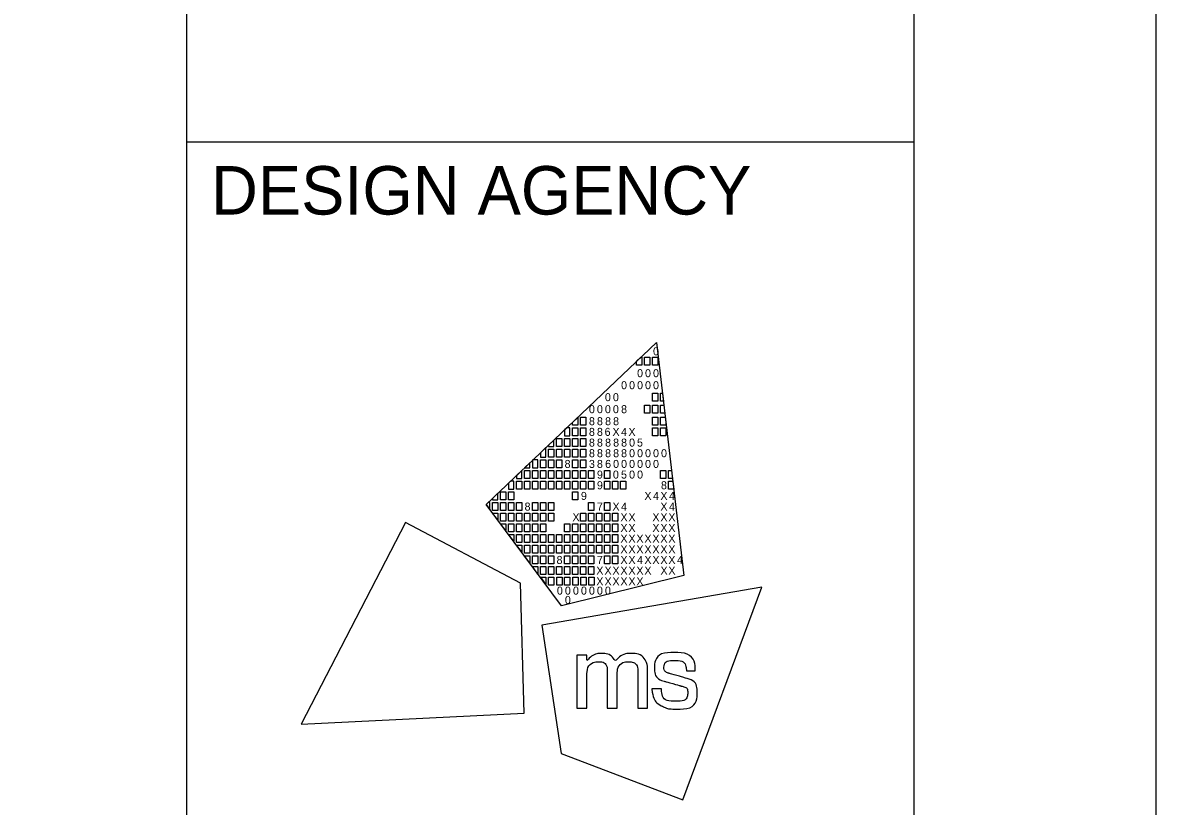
# Model space of a CAD drawing. Extents: x -3.4 to 34, y 0 to 22.
# Drawn here: x 31.661 to 34, y 3.129 to 4.746 of the extents above; entities that cross this region are included whole.
import ezdxf

# ---------------------------------------------------------------- set-up
doc = ezdxf.new("R2010")
doc.units = 0
for name, color, linetype in [('Default', 7, 'Continuous'), ('SH_Border', 7, 'Continuous'), ('SH_Cut_Line', 7, 'Continuous'), ('SH_Data', 7, 'Continuous')]:
    doc.layers.add(name, color=color, linetype=linetype)

msp = doc.modelspace()

# ---------------------------------------------------------------- linework, layer by layer
at = {"layer": 'Default'}
for p, q in [((32.6175, 3.7519), (32.9688, 4.0861)), ((32.9688, 4.0861), (32.9688, 4.0861)), ((32.9688, 4.0861), (33.0253, 3.6052)), ((32.773, 3.543), (32.6175, 3.7519)), ((33.0253, 3.6052), (32.773, 3.543))]:
    msp.add_line(p, q, dxfattribs=at)
for points in [[(32.9279, 4.0472), (32.9369, 4.0558), (32.9389, 4.0558), (32.9389, 4.0393), (32.9279, 4.0393)], [(32.9444, 4.0558), (32.9554, 4.0558), (32.9554, 4.0393), (32.9444, 4.0393)], [(32.9609, 4.0558), (32.9719, 4.0558), (32.9719, 4.0393), (32.9609, 4.0393)], [(32.9606, 3.9815), (32.9716, 3.9815), (32.9716, 3.965), (32.9606, 3.965)], [(32.9771, 3.9815), (32.9811, 3.9815), (32.983, 3.965), (32.9771, 3.965)], [(32.9441, 3.9567), (32.9551, 3.9567), (32.9551, 3.9402), (32.9441, 3.9402)], [(32.9606, 3.9567), (32.9716, 3.9567), (32.9716, 3.9402), (32.9606, 3.9402)], [(32.9771, 3.9567), (32.984, 3.9567), (32.9859, 3.9402), (32.9771, 3.9402)], [(32.7953, 3.9211), (32.8064, 3.9316), (32.8064, 3.9154), (32.7953, 3.9154)], [(32.8123, 3.9319), (32.8233, 3.9319), (32.8233, 3.9154), (32.8123, 3.9154)], [(32.9606, 3.9319), (32.9716, 3.9319), (32.9716, 3.9154), (32.9606, 3.9154)], [(32.9771, 3.9319), (32.9869, 3.9319), (32.9881, 3.9218), (32.9881, 3.9154), (32.9771, 3.9154)], [(32.7958, 3.9099), (32.8068, 3.9099), (32.8068, 3.8934), (32.7958, 3.8934)], [(32.8123, 3.9099), (32.8233, 3.9099), (32.8233, 3.8934), (32.8123, 3.8934)], [(32.9606, 3.9099), (32.9716, 3.9099), (32.9716, 3.8934), (32.9606, 3.8934)], [(32.9771, 3.9099), (32.9881, 3.9099), (32.9881, 3.8934), (32.9771, 3.8934)], [(32.7627, 3.8879), (32.7737, 3.8879), (32.7737, 3.8714), (32.7627, 3.8714)], [(32.7793, 3.8879), (32.7903, 3.8879), (32.7903, 3.8714), (32.7793, 3.8714)], [(32.7958, 3.8879), (32.8068, 3.8879), (32.8068, 3.8714), (32.7958, 3.8714)], [(32.8123, 3.8879), (32.8233, 3.8879), (32.8233, 3.8714), (32.8123, 3.8714)], [(32.7462, 3.8659), (32.7572, 3.8659), (32.7572, 3.8494), (32.7462, 3.8494)], [(32.7627, 3.8659), (32.7737, 3.8659), (32.7737, 3.8494), (32.7627, 3.8494)], [(32.7793, 3.8659), (32.7903, 3.8659), (32.7903, 3.8494), (32.7793, 3.8494)], [(32.7958, 3.8659), (32.8068, 3.8659), (32.8068, 3.8494), (32.7958, 3.8494)], [(32.8123, 3.8659), (32.8233, 3.8659), (32.8233, 3.8494), (32.8123, 3.8494)], [(32.7297, 3.8439), (32.7407, 3.8439), (32.7407, 3.8273), (32.7297, 3.8273)], [(32.7462, 3.8439), (32.7572, 3.8439), (32.7572, 3.8273), (32.7462, 3.8273)], [(32.7627, 3.8439), (32.7737, 3.8439), (32.7737, 3.8273), (32.7627, 3.8273)], [(32.7958, 3.8439), (32.8068, 3.8439), (32.8068, 3.8273), (32.7958, 3.8273)], [(32.8123, 3.8439), (32.8233, 3.8439), (32.8233, 3.8273), (32.8123, 3.8273)], [(32.6967, 3.8218), (32.7077, 3.8218), (32.7077, 3.8053), (32.6967, 3.8053)], [(32.7132, 3.8218), (32.7242, 3.8218), (32.7242, 3.8053), (32.7132, 3.8053)], [(32.7297, 3.8218), (32.7407, 3.8218), (32.7407, 3.8053), (32.7297, 3.8053)], [(32.7462, 3.8218), (32.7572, 3.8218), (32.7572, 3.8053), (32.7462, 3.8053)], [(32.7627, 3.8218), (32.7737, 3.8218), (32.7737, 3.8053), (32.7627, 3.8053)], [(32.7793, 3.8218), (32.7903, 3.8218), (32.7903, 3.8053), (32.7793, 3.8053)], [(32.7958, 3.8218), (32.8068, 3.8218), (32.8068, 3.8053), (32.7958, 3.8053)], [(32.8123, 3.8218), (32.8233, 3.8218), (32.8233, 3.8053), (32.8123, 3.8053)], [(32.8288, 3.8218), (32.8398, 3.8218), (32.8398, 3.8053), (32.8288, 3.8053)], [(32.8618, 3.8218), (32.8728, 3.8218), (32.8728, 3.8053), (32.8618, 3.8053)], [(32.9771, 3.8218), (32.9881, 3.8218), (32.9881, 3.8053), (32.9771, 3.8053)], [(32.9935, 3.8218), (32.9998, 3.8218), (33.0018, 3.8053), (32.9935, 3.8053)], [(32.6802, 3.7998), (32.6912, 3.7998), (32.6912, 3.7833), (32.6802, 3.7833)], [(32.6967, 3.7998), (32.7077, 3.7998), (32.7077, 3.7833), (32.6967, 3.7833)], [(32.7132, 3.7998), (32.7242, 3.7998), (32.7242, 3.7833), (32.7132, 3.7833)], [(32.7297, 3.7998), (32.7407, 3.7998), (32.7407, 3.7833), (32.7297, 3.7833)], [(32.7462, 3.7998), (32.7572, 3.7998), (32.7572, 3.7833), (32.7462, 3.7833)], [(32.7627, 3.7998), (32.7737, 3.7998), (32.7737, 3.7833), (32.7627, 3.7833)], [(32.7793, 3.7998), (32.7903, 3.7998), (32.7903, 3.7833), (32.7793, 3.7833)], [(32.7958, 3.7998), (32.8068, 3.7998), (32.8068, 3.7833), (32.7958, 3.7833)], [(32.8123, 3.7998), (32.8233, 3.7998), (32.8233, 3.7833), (32.8123, 3.7833)], [(32.8288, 3.7998), (32.8398, 3.7998), (32.8398, 3.7833), (32.8288, 3.7833)], [(32.8618, 3.7998), (32.8728, 3.7998), (32.8728, 3.7833), (32.8618, 3.7833)], [(32.8783, 3.7998), (32.8893, 3.7998), (32.8893, 3.7833), (32.8783, 3.7833)], [(32.8947, 3.7998), (32.9057, 3.7998), (32.9057, 3.7833), (32.8947, 3.7833)], [(32.9935, 3.7998), (33.0024, 3.7998), (33.0044, 3.7833), (32.9935, 3.7833)], [(32.6471, 3.7778), (32.6581, 3.7778), (32.6581, 3.7613), (32.6471, 3.7613)], [(32.6637, 3.7778), (32.6747, 3.7778), (32.6747, 3.7613), (32.6637, 3.7613)], [(32.7958, 3.7778), (32.8068, 3.7778), (32.8068, 3.7613), (32.7958, 3.7613)], [(32.6306, 3.7558), (32.6416, 3.7558), (32.6416, 3.7393), (32.6306, 3.7393)], [(32.6471, 3.7558), (32.6581, 3.7558), (32.6581, 3.7393), (32.6471, 3.7393)], [(32.6637, 3.7558), (32.6747, 3.7558), (32.6747, 3.7393), (32.6637, 3.7393)], [(32.6802, 3.7558), (32.6912, 3.7558), (32.6912, 3.7393), (32.6802, 3.7393)], [(32.7132, 3.7558), (32.7242, 3.7558), (32.7242, 3.7393), (32.7132, 3.7393)], [(32.7297, 3.7558), (32.7407, 3.7558), (32.7407, 3.7393), (32.7297, 3.7393)], [(32.7462, 3.7558), (32.7572, 3.7558), (32.7572, 3.7393), (32.7462, 3.7393)], [(32.8288, 3.7558), (32.8398, 3.7558), (32.8398, 3.7393), (32.8288, 3.7393)], [(32.8618, 3.7558), (32.8728, 3.7558), (32.8728, 3.7393), (32.8618, 3.7393)], [(32.6306, 3.7338), (32.6416, 3.7338), (32.6416, 3.72)], [(32.6471, 3.7338), (32.6581, 3.7338), (32.6581, 3.7173), (32.6471, 3.7173)], [(32.6637, 3.7338), (32.6747, 3.7338), (32.6747, 3.7173), (32.6637, 3.7173)], [(32.6802, 3.7338), (32.6912, 3.7338), (32.6912, 3.7173), (32.6802, 3.7173)], [(32.6967, 3.7338), (32.7077, 3.7338), (32.7077, 3.7173), (32.6967, 3.7173)], [(32.7132, 3.7338), (32.7242, 3.7338), (32.7242, 3.7173), (32.7132, 3.7173)], [(32.7297, 3.7338), (32.7407, 3.7338), (32.7407, 3.7173), (32.7297, 3.7173)], [(32.7462, 3.7338), (32.7572, 3.7338), (32.7572, 3.7173), (32.7462, 3.7173)], [(32.8123, 3.7338), (32.8233, 3.7338), (32.8233, 3.7173), (32.8123, 3.7173)], [(32.8288, 3.7338), (32.8398, 3.7338), (32.8398, 3.7173), (32.8288, 3.7173)], [(32.8453, 3.7338), (32.8563, 3.7338), (32.8563, 3.7173), (32.8453, 3.7173)], [(32.8618, 3.7338), (32.8728, 3.7338), (32.8728, 3.7173), (32.8618, 3.7173)], [(32.8783, 3.7338), (32.8893, 3.7338), (32.8893, 3.7173), (32.8783, 3.7173)], [(32.6471, 3.7117), (32.6581, 3.7117), (32.6581, 3.698)], [(32.6637, 3.7117), (32.6747, 3.7117), (32.6747, 3.6952), (32.6637, 3.6952)], [(32.6802, 3.7117), (32.6912, 3.7117), (32.6912, 3.6952), (32.6802, 3.6952)], [(32.6967, 3.7117), (32.7077, 3.7117), (32.7077, 3.6952), (32.6967, 3.6952)], [(32.7132, 3.7117), (32.7242, 3.7117), (32.7242, 3.6952), (32.7132, 3.6952)], [(32.7297, 3.7117), (32.7407, 3.7117), (32.7407, 3.6952), (32.7297, 3.6952)], [(32.7793, 3.7117), (32.7903, 3.7117), (32.7903, 3.6952), (32.7793, 3.6952)], [(32.7958, 3.7117), (32.8068, 3.7117), (32.8068, 3.6952), (32.7958, 3.6952)], [(32.8123, 3.7117), (32.8233, 3.7117), (32.8233, 3.6952), (32.8123, 3.6952)], [(32.8288, 3.7117), (32.8398, 3.7117), (32.8398, 3.6952), (32.8288, 3.6952)], [(32.8453, 3.7117), (32.8563, 3.7117), (32.8563, 3.6952), (32.8453, 3.6952)], [(32.8618, 3.7117), (32.8728, 3.7117), (32.8728, 3.6952), (32.8618, 3.6952)], [(32.8783, 3.7117), (32.8893, 3.7117), (32.8893, 3.6952), (32.8783, 3.6952)], [(32.6637, 3.6897), (32.6747, 3.6897), (32.6747, 3.676)], [(32.6747, 3.6897), (32.6747, 3.6897), (32.6747, 3.6897)], [(32.6802, 3.6897), (32.6912, 3.6897), (32.6912, 3.6732), (32.6802, 3.6732)], [(32.6967, 3.6897), (32.7077, 3.6897), (32.7077, 3.6732), (32.6967, 3.6732)], [(32.7132, 3.6897), (32.7242, 3.6897), (32.7242, 3.6732), (32.7132, 3.6732)], [(32.7297, 3.6897), (32.7407, 3.6897), (32.7407, 3.6732), (32.7297, 3.6732)], [(32.7462, 3.6897), (32.7572, 3.6897), (32.7572, 3.6732), (32.7462, 3.6732)], [(32.7627, 3.6897), (32.7737, 3.6897), (32.7737, 3.6732), (32.7627, 3.6732)], [(32.7793, 3.6897), (32.7903, 3.6897), (32.7903, 3.6732), (32.7793, 3.6732)], [(32.7958, 3.6897), (32.8068, 3.6897), (32.8068, 3.6732), (32.7958, 3.6732)], [(32.8123, 3.6897), (32.8233, 3.6897), (32.8233, 3.6732), (32.8123, 3.6732)], [(32.8288, 3.6897), (32.8398, 3.6897), (32.8398, 3.6732), (32.8288, 3.6732)], [(32.8453, 3.6897), (32.8563, 3.6897), (32.8563, 3.6732), (32.8453, 3.6732)], [(32.8618, 3.6897), (32.8728, 3.6897), (32.8728, 3.6732), (32.8618, 3.6732)], [(32.8783, 3.6897), (32.8893, 3.6897), (32.8893, 3.6732), (32.8783, 3.6732)], [(32.6802, 3.6677), (32.6912, 3.6677), (32.6912, 3.654)], [(32.6967, 3.6677), (32.7077, 3.6677), (32.7077, 3.6512), (32.6967, 3.6512)], [(32.7132, 3.6677), (32.7242, 3.6677), (32.7242, 3.6512), (32.7132, 3.6512)], [(32.7297, 3.6677), (32.7407, 3.6677), (32.7407, 3.6512), (32.7297, 3.6512)], [(32.7462, 3.6677), (32.7572, 3.6677), (32.7572, 3.6512), (32.7462, 3.6512)], [(32.7627, 3.6677), (32.7737, 3.6677), (32.7737, 3.6512), (32.7627, 3.6512)], [(32.7793, 3.6677), (32.7903, 3.6677), (32.7903, 3.6512), (32.7793, 3.6512)], [(32.7958, 3.6677), (32.8068, 3.6677), (32.8068, 3.6512), (32.7958, 3.6512)], [(32.8123, 3.6677), (32.8233, 3.6677), (32.8233, 3.6512), (32.8123, 3.6512)], [(32.8288, 3.6677), (32.8398, 3.6677), (32.8398, 3.6512), (32.8288, 3.6512)], [(32.8453, 3.6677), (32.8563, 3.6677), (32.8563, 3.6512), (32.8453, 3.6512)], [(32.8618, 3.6677), (32.8728, 3.6677), (32.8728, 3.6512), (32.8618, 3.6512)], [(32.8783, 3.6677), (32.8893, 3.6677), (32.8893, 3.6512), (32.8783, 3.6512)], [(32.7077, 3.6305), (32.6965, 3.6457), (32.7077, 3.6457)], [(32.7132, 3.6457), (32.7242, 3.6457), (32.7242, 3.6292), (32.7132, 3.6292)], [(32.7297, 3.6457), (32.7407, 3.6457), (32.7407, 3.6292), (32.7297, 3.6292)], [(32.7462, 3.6457), (32.7572, 3.6457), (32.7572, 3.6292), (32.7462, 3.6292)], [(32.7793, 3.6457), (32.7903, 3.6457), (32.7903, 3.6292), (32.7793, 3.6292)], [(32.7958, 3.6457), (32.8068, 3.6457), (32.8068, 3.6292), (32.7958, 3.6292)], [(32.8123, 3.6457), (32.8233, 3.6457), (32.8233, 3.6292), (32.8123, 3.6292)], [(32.8288, 3.6457), (32.8398, 3.6457), (32.8398, 3.6292), (32.8288, 3.6292)], [(32.8618, 3.6457), (32.8728, 3.6457), (32.8728, 3.6292), (32.8618, 3.6292)], [(32.8783, 3.6457), (32.8893, 3.6457), (32.8893, 3.6292), (32.8783, 3.6292)], [(32.724, 3.6082), (32.7132, 3.6237), (32.7242, 3.6237)], [(32.7297, 3.6237), (32.7407, 3.6237), (32.7407, 3.6072), (32.7297, 3.6072)], [(32.7302, 3.6017), (32.7407, 3.6017), (32.7408, 3.5875)], [(32.7462, 3.6237), (32.7572, 3.6237), (32.7572, 3.6072), (32.7462, 3.6072)], [(32.7463, 3.6017), (32.7573, 3.6017), (32.7573, 3.5852), (32.7463, 3.5852)], [(32.7627, 3.6237), (32.7737, 3.6237), (32.7737, 3.6072), (32.7627, 3.6072)], [(32.763, 3.6017), (32.774, 3.6017), (32.774, 3.5852), (32.763, 3.5852)], [(32.7793, 3.6237), (32.7903, 3.6237), (32.7903, 3.6072), (32.7793, 3.6072)], [(32.7794, 3.6017), (32.7904, 3.6017), (32.7904, 3.5852), (32.7794, 3.5852)], [(32.7958, 3.6237), (32.8068, 3.6237), (32.8068, 3.6072), (32.7958, 3.6072)], [(32.796, 3.6017), (32.807, 3.6017), (32.807, 3.5852), (32.796, 3.5852)], [(32.8123, 3.6237), (32.8233, 3.6237), (32.8233, 3.6072), (32.8123, 3.6072)], [(32.8129, 3.6017), (32.8239, 3.6017), (32.8239, 3.5851), (32.8129, 3.5851)], [(32.8288, 3.6237), (32.8398, 3.6237), (32.8398, 3.6072), (32.8288, 3.6072)], [(32.8296, 3.6017), (32.8406, 3.6017), (32.8406, 3.5851), (32.8296, 3.5851)]]:
    msp.add_lwpolyline(points, close=True, dxfattribs=at)
for points in [[(32.7903, 3.9099), (32.7836, 3.9099), (32.7793, 3.9058), (32.7793, 3.8934), (32.7903, 3.8934), (32.7903, 3.9099)], [(32.7572, 3.8849), (32.7462, 3.8744), (32.7462, 3.8714), (32.7572, 3.8714), (32.7572, 3.8849)], [(32.7407, 3.8691), (32.7297, 3.8587), (32.7297, 3.8494), (32.7407, 3.8494), (32.7407, 3.8691)], [(32.7077, 3.8377), (32.6968, 3.8273), (32.7077, 3.8273), (32.7077, 3.8377)], [(32.7242, 3.8439), (32.7141, 3.8439), (32.7132, 3.843), (32.7132, 3.8273), (32.7242, 3.8273), (32.7242, 3.8439)], [(32.6912, 3.822), (32.6802, 3.8115), (32.6802, 3.8053), (32.6912, 3.8053), (32.6912, 3.822)], [(32.6747, 3.7998), (32.6679, 3.7998), (32.6637, 3.7958), (32.6637, 3.7833), (32.6747, 3.7833), (32.6747, 3.7998)], [(32.6416, 3.7749), (32.6306, 3.7644), (32.6306, 3.7613), (32.6416, 3.7613), (32.6416, 3.7749)], [(32.6251, 3.7558), (32.6216, 3.7558), (32.6175, 3.7519), (32.6251, 3.7417), (32.6251, 3.7558)], [(32.4512, 3.7149), (32.2359, 3.2988), (32.6956, 3.3215), (32.6884, 3.5892), (32.4512, 3.7149)], [(33.0229, 3.1422), (33.1859, 3.5814), (32.7324, 3.5029), (32.7722, 3.2381), (33.0229, 3.1422)]]:
    msp.add_lwpolyline(points, dxfattribs=at)
for points in [[(32.8048, 3.3315), (32.8048, 3.3315), (32.8048, 3.4409), (32.8048, 3.4409), (32.8048, 3.4409), (32.8255, 3.4409), (32.8255, 3.4409), (32.8255, 3.4409), (32.8255, 3.4297), (32.8255, 3.4297), (32.8346, 3.4399), (32.8457, 3.4445), (32.8555, 3.4445), (32.8688, 3.4445), (32.8791, 3.4372), (32.8837, 3.4266), (32.8915, 3.4381), (32.905, 3.4446), (32.9166, 3.4446), (32.9325, 3.4446), (32.9451, 3.435), (32.9494, 3.4213), (32.9494, 3.4212), (32.9494, 3.4212), (32.9494, 3.4212), (32.9501, 3.419), (32.9506, 3.4172), (32.9506, 3.4071), (32.9506, 3.4071), (32.9506, 3.3314), (32.9506, 3.3314), (32.9506, 3.3314), (32.9303, 3.3314), (32.9303, 3.3314), (32.9303, 3.3314), (32.9303, 3.4048), (32.9303, 3.4048), (32.9303, 3.4201), (32.9219, 3.4274), (32.911, 3.4274), (32.8995, 3.4274), (32.8879, 3.4171), (32.8879, 3.4001), (32.8879, 3.4001), (32.8879, 3.3315), (32.8879, 3.3315), (32.8879, 3.3315), (32.8674, 3.3315), (32.8674, 3.3315), (32.8674, 3.3315), (32.8674, 3.4059), (32.8674, 3.4059), (32.8674, 3.4203), (32.8588, 3.4274), (32.8496, 3.4274), (32.8384, 3.4274), (32.8254, 3.417), (32.8254, 3.3962), (32.8254, 3.3962), (32.8254, 3.3315), (32.8254, 3.3315), (32.8254, 3.3315), (32.8048, 3.3315), (32.8048, 3.3315)], [(32.9595, 3.3709), (32.9595, 3.3709), (32.9595, 3.3717), (32.9595, 3.3717), (32.9595, 3.3717), (32.9603, 3.3717), (32.9603, 3.3717), (32.9603, 3.3717), (32.9783, 3.3717), (32.9783, 3.3717), (32.9783, 3.3717), (32.9789, 3.3717), (32.9789, 3.3717), (32.9789, 3.3717), (32.979, 3.371), (32.979, 3.371), (32.9803, 3.3554), (32.9887, 3.346), (33.009, 3.346), (33.0273, 3.346), (33.0333, 3.3554), (33.0333, 3.3631), (33.0333, 3.3732), (33.0256, 3.3758), (33.0175, 3.378), (33.0175, 3.378), (32.987, 3.3867), (32.987, 3.3867), (32.972, 3.3909), (32.9648, 3.4019), (32.9648, 3.4142), (32.9648, 3.4303), (32.9768, 3.4462), (33.0052, 3.4462), (33.0348, 3.4462), (33.0489, 3.4285), (33.0489, 3.4095), (33.0489, 3.4095), (33.0489, 3.4087), (33.0489, 3.4087), (33.0489, 3.4087), (33.0482, 3.4087), (33.0482, 3.4087), (33.0482, 3.4087), (33.0312, 3.4087), (33.0312, 3.4087), (33.0312, 3.4087), (33.0305, 3.4087), (33.0305, 3.4087), (33.0305, 3.4087), (33.0305, 3.4094), (33.0305, 3.4094), (33.0301, 3.4208), (33.0226, 3.43), (33.0056, 3.43), (32.9891, 3.43), (32.9843, 3.4218), (32.9843, 3.4157), (32.9843, 3.4108), (32.9869, 3.4059), (32.9959, 3.4033), (32.9959, 3.4033), (33.0255, 3.3948), (33.0255, 3.3948), (33.0462, 3.3889), (33.0527, 3.3777), (33.0527, 3.3639), (33.0527, 3.3462), (33.041, 3.3298), (33.0087, 3.3298), (32.9952, 3.3298), (32.9877, 3.3321), (32.9823, 3.3348), (32.969, 3.3414), (32.9609, 3.3536), (32.9595, 3.3709)]]:
    msp.add_open_spline(points, degree=3, dxfattribs=at)
at = {"layer": 'SH_Border'}
for p, q in [((32, 0.5), (32, 21.5)), ((32, 4.5), (33.5, 4.5))]:
    msp.add_line(p, q, dxfattribs=at)
msp.add_lwpolyline([(1.5, 21.5), (33.5, 21.5), (33.5, 0.5), (1.5, 0.5)], close=True, dxfattribs=at)
at = {"layer": 'SH_Cut_Line'}
msp.add_lwpolyline([(0, 0), (34, 0), (34, 22), (0, 22)], close=True, dxfattribs=at)
at = {"layer": 'SH_Data'}
msp.add_line((32.75, 3.5), (32.75, 3.5), dxfattribs=at)

# ---------------------------------------------------------------- texts
at = {"layer": 'Default'}
for s, p in [('0', (32.9617, 4.0597)), ('0', (32.9288, 4.0145)), ('0', (32.9452, 4.0145)), ('0', (32.9617, 4.0145)), ('0', (32.8958, 3.9897)), ('0', (32.9123, 3.9897)), ('0', (32.9288, 3.9897)), ('0', (32.9452, 3.9897)), ('0', (32.9617, 3.9897)), ('0', (32.8625, 3.965)), ('0', (32.879, 3.965)), ('0', (32.8295, 3.9402)), ('0', (32.846, 3.9402)), ('0', (32.8625, 3.9402)), ('0', (32.879, 3.9402)), ('8', (32.8958, 3.9402)), ('8', (32.8295, 3.9154)), ('8', (32.846, 3.9154)), ('8', (32.8628, 3.9154)), ('8', (32.8793, 3.9154)), ('8', (32.8295, 3.8934)), ('8', (32.846, 3.8934)), ('6', (32.8618, 3.8934)), ('X', (32.8781, 3.8934)), ('4', (32.8958, 3.8934)), ('X', (32.911, 3.8934)), ('8', (32.8295, 3.8713)), ('8', (32.846, 3.8713)), ('8', (32.8628, 3.8713)), ('8', (32.8794, 3.8713)), ('8', (32.8958, 3.8713)), ('0', (32.9123, 3.8713)), ('5', (32.9287, 3.8713)), ('8', (32.8295, 3.8494)), ('8', (32.846, 3.8494)), ('8', (32.8628, 3.8494)), ('8', (32.8794, 3.8494)), ('8', (32.8958, 3.8494)), ('0', (32.9123, 3.8494)), ('0', (32.9288, 3.8494)), ('0', (32.9452, 3.8494)), ('0', (32.9617, 3.8494)), ('0', (32.9782, 3.8494)), ('8', (32.7793, 3.8273)), ('3', (32.8295, 3.8273)), ('8', (32.846, 3.8273)), ('6', (32.8629, 3.8273)), ('0', (32.8793, 3.8273)), ('0', (32.8958, 3.8273)), ('0', (32.9123, 3.8273)), ('0', (32.9288, 3.8273)), ('0', (32.9452, 3.8273)), ('0', (32.9617, 3.8273)), ('9', (32.846, 3.8053)), ('0', (32.879, 3.8053)), ('5', (32.8957, 3.8053)), ('0', (32.9123, 3.8053)), ('0', (32.9288, 3.8053)), ('9', (32.846, 3.7833)), ('8', (32.9781, 3.7833)), ('9', (32.813, 3.7613)), ('X', (32.9439, 3.7613)), ('4', (32.9617, 3.7613)), ('X', (32.9769, 3.7613)), ('4', (32.9946, 3.7613)), ('8', (32.6967, 3.7393)), ('7', (32.846, 3.7393)), ('X', (32.8781, 3.7393)), ('4', (32.8958, 3.7393)), ('X', (32.9769, 3.7393)), ('4', (32.9946, 3.7393)), ('X', (32.7955, 3.7173)), ('X', (32.8945, 3.7173)), ('X', (32.911, 3.7173)), ('X', (32.9604, 3.7173)), ('X', (32.9769, 3.7173)), ('X', (32.9933, 3.7173)), ('X', (32.8945, 3.6952)), ('X', (32.911, 3.6952)), ('X', (32.9604, 3.6952)), ('X', (32.9769, 3.6952)), ('X', (32.9933, 3.6952)), ('X', (32.8945, 3.6732)), ('X', (32.911, 3.6732)), ('X', (32.9274, 3.6732)), ('X', (32.9439, 3.6732)), ('X', (32.9604, 3.6732)), ('X', (32.9769, 3.6732)), ('X', (32.9933, 3.6732)), ('X', (32.8945, 3.6512)), ('X', (32.911, 3.6512)), ('X', (32.9274, 3.6512)), ('X', (32.9439, 3.6512)), ('X', (32.9604, 3.6512)), ('X', (32.9769, 3.6512)), ('X', (32.9933, 3.6512)), ('8', (32.7627, 3.6292)), ('7', (32.846, 3.6292)), ('X', (32.8945, 3.6292)), ('X', (32.911, 3.6292)), ('4', (32.9288, 3.6292)), ('X', (32.9439, 3.6292)), ('X', (32.9604, 3.6292)), ('X', (32.9769, 3.6292)), ('X', (32.9933, 3.6292)), ('4', (33.0111, 3.6292)), ('X', (32.8447, 3.6072)), ('X', (32.8447, 3.5851)), ('X', (32.8616, 3.6072)), ('X', (32.8616, 3.5851)), ('X', (32.878, 3.6072)), ('X', (32.878, 3.5851)), ('X', (32.8945, 3.6072)), ('X', (32.8945, 3.5851)), ('X', (32.911, 3.6072)), ('X', (32.911, 3.5851)), ('X', (32.9274, 3.6072)), ('X', (32.9274, 3.5851)), ('X', (32.9439, 3.6072)), ('X', (32.9771, 3.6072)), ('X', (32.9933, 3.6072)), ('0', (32.7634, 3.5659)), ('0', (32.7799, 3.5659)), ('0', (32.7965, 3.5659)), ('0', (32.813, 3.5659)), ('0', (32.8295, 3.5659)), ('0', (32.846, 3.5659)), ('0', (32.8625, 3.5659)), ('0', (32.7799, 3.5467))]:
    msp.add_text(s, height=0.0165, rotation=360, dxfattribs=at).set_placement(p)
at = {"layer": 'SH_Data'}
msp.add_text('DESIGN AGENCY', height=0.1, dxfattribs=at).set_placement((32.05, 4.35))

doc.saveas('drawing.dxf')
